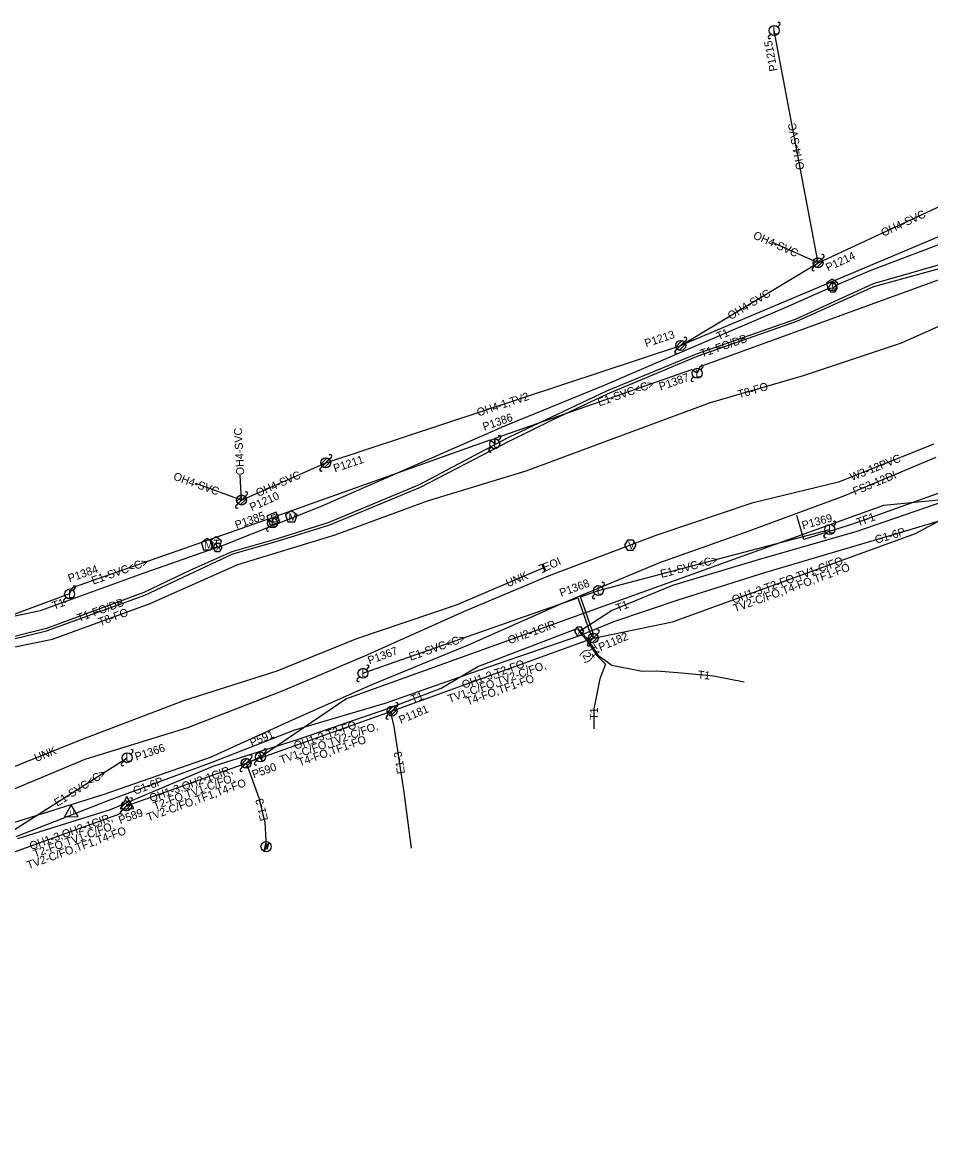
# Model space of a CAD drawing. Extents: x 2336688 to 2352634, y 362473 to 369571.
# Drawn here: x 2350587 to 2351041, y 368310 to 368866 of the extents above; entities that cross this region are included whole.
import ezdxf

# ---------------------------------------------------------------- set-up
doc = ezdxf.new("R2010")
doc.units = 0
for name, color, linetype in [('RD_EX_DV_Prop', 7, 'Continuous'), ('RD_EX_DV_TX_Prop', 7, 'Continuous'), ('RD_EX_RW', 7, 'Continuous'), ('RD_EX_RW_TX', 7, 'Continuous'), ('RD_HC_CL_Rel', 7, 'Continuous'), ('RD_HC_Data_Tic', 7, 'Continuous'), ('RD_PD_CstnLmt', 7, 'Continuous'), ('RD_PD_Final_TrvlWay', 7, 'Continuous'), ('RD_PD_Final_TX', 7, 'Continuous'), ('RD_PD_FOC', 7, 'Continuous'), ('RD_PD_PatLn2', 7, 'Continuous'), ('RD_PD_PatLn3', 7, 'Continuous'), ('RD_PD_PatLn4', 7, 'Continuous'), ('RD_SHT_ShtClip', 7, 'Continuous'), ('RD_Sketch1', 7, 'Continuous'), ('RD_Sketch2', 7, 'Continuous'), ('RD_Sketch5', 7, 'Continuous'), ('RD_Sketch8', 7, 'Continuous')]:
    doc.layers.add(name, color=color, linetype=linetype)

msp = doc.modelspace()

# ---------------------------------------------------------------- linework, layer by layer
at = {"layer": 'RD_EX_RW_TX'}
msp.add_line((2350684.98, 368603.53), (2350684.15, 368605.9), dxfattribs=at)
for points in [[(2350547.98, 368561.97), (2350596.49, 368572.11), (2350646, 368590.01), (2350683.45, 368603.19), (2350684.98, 368603.53), (2350685.71, 368603.81), (2350737.28, 368624.33), (2350782.62, 368644.22), (2350828.45, 368664.29), (2350878.61, 368684.87), (2350923.16, 368704), (2350969.39, 368723.81), (2350990.05, 368732.94), (2350992.44, 368733.22), (2350994.4, 368734.75), (2351011.06, 368741.96), (2351053.69, 368758.05)], [(2351057.77, 368748.3), (2351012.48, 368735.27), (2350973.53, 368717.4), (2350924.13, 368700.19), (2350879.33, 368681.7), (2350851.85, 368668.58), (2350829.97, 368658.39), (2350785.64, 368634.8), (2350740.56, 368616.04), (2350714.28, 368607.77), (2350692.2, 368601.39), (2350671.06, 368591.99), (2350648.19, 368580.98), (2350599.46, 368563.03), (2350571.6, 368556.05)], [(2350571.6, 368555.09), (2350599.59, 368561.91), (2350648.7, 368579.74), (2350692.54, 368600.36), (2350714.31, 368606.56), (2350741.1, 368614.8), (2350786.33, 368633.63), (2350830.68, 368656.6), (2350852.32, 368667.35), (2350879.75, 368680.28), (2350925.14, 368699.29), (2350974.31, 368716.57), (2351012.91, 368733.98), (2351058.97, 368746.67)], [(2350171.87, 368427.87), (2350217.94, 368444.86), (2350264.95, 368459.5), (2350312.55, 368474.5), (2350359.96, 368486.74), (2350398.97, 368499.58), (2350441.96, 368515.14), (2350504.54, 368534.47), (2350552.41, 368547.56), (2350602.53, 368557.75), (2350651.32, 368575.57), (2350695.05, 368595.12), (2350743.66, 368609.85), (2350789.93, 368626.9), (2350839.13, 368641.87), (2350884.51, 368658.74), (2350931.21, 368675.96), (2350977.7, 368689.48), (2351026.67, 368705.73), (2351072.69, 368726.31)], [(2350585.17, 368458.19), (2350631.55, 368472.55), (2350682.78, 368494.32), (2350725.46, 368507.84), (2350770.6, 368523.34), (2350796.76, 368533.17), (2350815.03, 368544.06), (2350864.65, 368563.02), (2350865.66, 368561.79), (2350866.64, 368562.26), (2350881.84, 368572.1), (2350912.46, 368584.65), (2350955.27, 368597.58), (2351004.61, 368611.63), (2351052.31, 368628.22)], [(2350865.66, 368561.79), (2350866.24, 368560.81), (2350868.94, 368557.77), (2350874.45, 368549.5), (2350878.83, 368545.22), (2350875.98, 368537.96), (2350872.99, 368522.86), (2350872.95, 368512.91)], [(2350865.66, 368561.79), (2350866.73, 368561.13), (2350869.44, 368558.17), (2350874.96, 368549.82), (2350881.96, 368544.69), (2350897.07, 368541.72), (2350904.37, 368541.89), (2350916.72, 368540.87), (2350932.83, 368539.33), (2350948.14, 368536.41)]]:
    msp.add_lwpolyline(points, dxfattribs=at)
for points in [[(2350991.99, 368737.61), (2350989.14, 368735.54), (2350990.23, 368732.19), (2350993.76, 368732.19), (2350994.85, 368735.54)], [(2350994.75, 368733.22), (2350993.59, 368735.22), (2350991.28, 368735.22), (2350990.13, 368733.22), (2350991.28, 368731.22), (2350993.59, 368731.22)], [(2350684.15, 368608.9), (2350681.29, 368606.83), (2350682.38, 368603.48), (2350685.91, 368603.48), (2350687, 368606.83)], [(2350687.29, 368603.53), (2350686.14, 368605.53), (2350683.83, 368605.53), (2350682.67, 368603.53), (2350683.83, 368601.53), (2350686.14, 368601.53)], [(2350867.97, 368561.79), (2350866.82, 368563.79), (2350864.51, 368563.79), (2350863.35, 368561.79), (2350864.51, 368559.79), (2350866.82, 368559.79)]]:
    msp.add_lwpolyline(points, close=True, dxfattribs=at)
at = {"layer": 'RD_HC_CL_Rel'}
msp.add_lwpolyline([(2350584.33, 368459.13), (2350630.35, 368477.17), (2350682.33, 368496.26), (2350723.55, 368512.36), (2350768.67, 368525.76), (2350815.63, 368542.18), (2350865.48, 368559.39), (2350883.5, 368566.67), (2350915.06, 368577.38), (2350958.43, 368591), (2351006.87, 368605.31), (2351056.9, 368620.23)], dxfattribs=at)
at = {"layer": 'RD_HC_Data_Tic'}
for p, q in [((2350964.86, 368863.63), (2350965.92, 368864.69)), ((2350960.27, 368859.04), (2350961.33, 368860.1)), ((2350982.56, 368745.17), (2350985.62, 368748.23)), ((2350983.21, 368744.05), (2350986.74, 368747.58)), ((2350986.74, 368747.58), (2350987.8, 368748.65)), ((2350982.14, 368742.99), (2350983.21, 368744.05)), ((2350984.33, 368743.4), (2350987.39, 368746.46)), ((2350913.55, 368701.66), (2350914.61, 368702.72)), ((2350913.96, 368703.84), (2350917.02, 368706.9)), ((2350914.61, 368702.72), (2350918.14, 368706.26)), ((2350915.73, 368702.08), (2350918.79, 368705.14)), ((2350918.14, 368706.26), (2350919.21, 368707.32)), ((2350926.36, 368692.34), (2350927.42, 368693.4)), ((2350921.76, 368687.74), (2350922.82, 368688.8)), ((2350825.22, 368657.13), (2350826.28, 368658.19)), ((2350820.62, 368652.53), (2350821.68, 368653.59)), ((2350736.61, 368645.21), (2350739.67, 368648.27)), ((2350737.26, 368644.09), (2350740.79, 368647.62)), ((2350740.79, 368647.62), (2350741.85, 368648.68)), ((2350736.19, 368643.03), (2350737.26, 368644.09)), ((2350738.38, 368643.44), (2350741.44, 368646.5)), ((2350694.15, 368624.44), (2350695.21, 368625.5)), ((2350694.56, 368626.62), (2350697.62, 368629.69)), ((2350695.21, 368625.5), (2350698.74, 368629.04)), ((2350696.33, 368624.86), (2350699.39, 368627.92)), ((2350698.74, 368629.04), (2350699.8, 368630.1)), ((2350709.6, 368612.99), (2350710.66, 368614.05)), ((2350714.19, 368617.58), (2350715.25, 368618.64)), ((2350992.61, 368614.3), (2350993.67, 368615.36)), ((2350988.01, 368609.7), (2350989.07, 368610.76)), ((2350612.86, 368582.08), (2350613.92, 368583.14)), ((2350872.4, 368579.2), (2350873.46, 368580.26)), ((2350876.99, 368583.8), (2350878.05, 368584.86)), ((2350608.26, 368577.48), (2350609.32, 368578.55)), ((2350870.31, 368557.66), (2350873.37, 368560.72)), ((2350870.95, 368556.54), (2350874.49, 368560.07)), ((2350872.07, 368555.89), (2350875.14, 368558.95)), ((2350874.49, 368560.07), (2350875.55, 368561.13)), ((2350869.89, 368555.48), (2350870.95, 368556.54)), ((2350759.39, 368542.45), (2350760.45, 368543.51)), ((2350754.8, 368537.86), (2350755.86, 368538.92)), ((2350773.92, 368523.58), (2350774.98, 368524.64)), ((2350769.32, 368518.98), (2350770.38, 368520.04)), ((2350769.73, 368521.16), (2350772.8, 368524.22)), ((2350770.38, 368520.04), (2350773.92, 368523.58)), ((2350771.5, 368519.39), (2350774.56, 368522.46)), ((2350637.02, 368495.69), (2350638.08, 368496.75)), ((2350641.61, 368500.29), (2350642.67, 368501.35)), ((2350696.8, 368495.06), (2350699.86, 368498.12)), ((2350697.45, 368493.94), (2350700.98, 368497.47)), ((2350700.98, 368497.47), (2350702.04, 368498.53)), ((2350703.56, 368496.05), (2350704.63, 368497.11)), ((2350708.16, 368500.65), (2350709.22, 368501.71)), ((2350696.39, 368492.88), (2350697.45, 368493.94)), ((2350698.57, 368493.29), (2350701.63, 368496.35)), ((2350637.03, 368473.78), (2350640.09, 368476.84)), ((2350637.68, 368472.66), (2350641.21, 368476.19)), ((2350638.8, 368472.01), (2350641.86, 368475.07)), ((2350641.21, 368476.19), (2350642.28, 368477.25)), ((2350636.62, 368471.6), (2350637.68, 368472.66))]:
    msp.add_line(p, q, dxfattribs=at)
msp.add_lwpolyline([(2350706, 368500.89), (2350706.83, 368498.87), (2350705.37, 368499.68), (2350707.24, 368496.99), (2350707.24, 368496.99), (2350706.04, 368499.09), (2350707.42, 368498.29)], close=True, dxfattribs=at)
for centre in [(2350963.09, 368861.87), (2350984.97, 368745.82), (2350916.38, 368704.49), (2350924.59, 368690.57), (2350823.45, 368655.36), (2350739.02, 368645.86), (2350696.97, 368627.27), (2350712.43, 368615.82), (2350990.84, 368612.53), (2350611.09, 368580.31), (2350875.22, 368582.03), (2350872.72, 368558.3), (2350757.63, 368540.68), (2350772.15, 368521.81), (2350639.85, 368498.52), (2350699.22, 368495.71), (2350706.39, 368498.88), (2350639.45, 368474.42)]:
    msp.add_circle(centre, 2.5, dxfattribs=at)
for centre, start, end in [((2350965.39, 368865.22), 315, 135), ((2350960.8, 368858.51), 135, 315), ((2350987.27, 368749.18), 315, 135), ((2350982.67, 368742.46), 135, 315), ((2350918.68, 368707.85), 315, 135), ((2350914.08, 368701.13), 135, 315), ((2350926.89, 368693.93), 315, 135), ((2350922.29, 368687.21), 135, 315), ((2350825.75, 368658.72), 315, 135), ((2350821.15, 368652), 135, 315), ((2350741.32, 368649.21), 315, 135), ((2350736.72, 368642.5), 135, 315), ((2350699.27, 368630.63), 315, 135), ((2350694.68, 368623.91), 135, 315), ((2350714.72, 368619.17), 315, 135), ((2350993.14, 368615.89), 315, 135), ((2350710.13, 368612.46), 135, 315), ((2350988.54, 368609.17), 135, 315), ((2350877.52, 368585.39), 315, 135), ((2350613.39, 368583.67), 315, 135), ((2350608.79, 368576.95), 135, 315), ((2350872.93, 368578.67), 135, 315), ((2350875.02, 368561.66), 315, 135), ((2350870.42, 368554.95), 135, 315), ((2350759.92, 368544.04), 315, 135), ((2350755.33, 368537.33), 135, 315), ((2350774.45, 368525.17), 315, 135), ((2350769.85, 368518.45), 135, 315), ((2350642.14, 368501.88), 315, 135), ((2350708.69, 368502.24), 315, 135), ((2350701.51, 368499.06), 315, 135), ((2350637.55, 368495.16), 135, 315), ((2350696.92, 368492.35), 135, 315), ((2350704.09, 368495.52), 135, 315), ((2350641.75, 368477.78), 315, 135), ((2350637.15, 368471.07), 135, 315)]:
    msp.add_arc(centre, 0.75, start, end, dxfattribs=at)
at = {"layer": 'RD_PD_Final_TrvlWay'}
for points in [[(2351152.66, 368771.86), (2351150.34, 368773.72), (2351066.03, 368744.69), (2351065.02, 368741.68), (2351062.36, 368743.39), (2350925.92, 368693.73), (2350924.59, 368690.57), (2350921.77, 368692.25), (2350823.59, 368658.07), (2350823.45, 368655.36), (2350821.04, 368657.17), (2350712.58, 368618.54), (2350712.43, 368615.82), (2350710.28, 368617.73), (2350612.32, 368583.41), (2350611.09, 368580.31), (2350556.98, 368560.45), (2350499.18, 368544.19), (2350503.41, 368546.65), (2350527.75, 368553.5), (2350557.82, 368562.03), (2350555.37, 368575.95), (2350556.68, 368579.27)], [(2350757.63, 368540.68), (2350864.91, 368578.41), (2350871.14, 368560.68), (2350872.72, 368558.3), (2350872.46, 368561.15), (2350866.23, 368578.87), (2350875.22, 368582.03), (2350990.84, 368612.53)], [(2350772.15, 368521.81), (2350771.61, 368520.42), (2350773.07, 368514.08), (2350778.11, 368481.36), (2350781.65, 368453.29)], [(2350529.28, 368444.39), (2350575.55, 368457.63), (2350639.85, 368498.52)], [(2350699.22, 368495.71), (2350699.82, 368494.64), (2350705.56, 368478.53), (2350708.55, 368466.06), (2350709.23, 368454.06)]]:
    msp.add_lwpolyline(points, dxfattribs=at)
for points in [[(2350714.33, 368621.13), (2350709.63, 368619.42), (2350711.34, 368614.72), (2350716.03, 368616.43)], [(2350710.62, 368456.12), (2350709.61, 368452.67), (2350709.11, 368454.54), (2350708.35, 368451.71), (2350709.04, 368455.62), (2350709.6, 368453.68)]]:
    msp.add_lwpolyline(points, close=True, dxfattribs=at)
msp.add_circle((2350709.23, 368454.06), 2.55, dxfattribs=at)
at = {"layer": 'RD_PD_PatLn3'}
for points in [[(2350569.2, 368488.37), (2350617.02, 368507.64), (2350668.18, 368527.03), (2350714.72, 368541.98), (2350754.57, 368558.07), (2350804.34, 368574.84), (2350847.72, 368593.34)], [(2350845.55, 368594.59), (2350846.93, 368595.18), (2350848.5, 368591.5), (2350847.12, 368590.91)]]:
    msp.add_lwpolyline(points, dxfattribs=at)
for points in [[(2350611.88, 368475.01), (2350608.5, 368468.97), (2350615.43, 368469.06)], [(2350639.66, 368479.07), (2350636.28, 368473.03), (2350643.2, 368473.12)]]:
    msp.add_lwpolyline(points, close=True, dxfattribs=at)
at = {"layer": 'RD_SHT_ShtClip'}
for p, q in [((2350984.97, 368745.82), (2350963.09, 368861.87)), ((2351197.21, 368822.78), (2350916.38, 368704.49)), ((2350984.97, 368745.82), (2351070.54, 368785.56)), ((2350984.97, 368745.82), (2350961.83, 368756.06)), ((2350916.38, 368704.49), (2350984.97, 368745.82)), ((2350739.02, 368645.86), (2350916.38, 368704.49)), ((2350696.97, 368627.27), (2350739.02, 368645.86)), ((2350696.97, 368627.27), (2350696.34, 368639.63)), ((2350696.97, 368627.27), (2350674.05, 368635.54)), ((2350872.72, 368558.3), (2350772.15, 368521.81)), ((2350772.15, 368521.81), (2350699.22, 368495.71)), ((2350699.22, 368495.71), (2350706.39, 368498.88)), ((2350639.45, 368474.42), (2350699.22, 368495.71))]:
    msp.add_line(p, q, dxfattribs=at)
for points in [[(2350706.39, 368498.88), (2350749.08, 368527.9), (2351017.85, 368624.75), (2351069.24, 368629.63)], [(2350872.72, 368558.3), (2350912.32, 368566.46), (2351033.64, 368610.49), (2351069.24, 368629.63)], [(2350577.9, 368452.25), (2350583.51, 368451.44), (2350635.64, 368470.23), (2350639.45, 368474.42)]]:
    msp.add_lwpolyline(points, dxfattribs=at)
at = {"layer": 'RD_Sketch2'}
msp.add_lwpolyline([(2351042.86, 368655.18), (2350995.25, 368636.19), (2350951.94, 368625.72), (2350904.41, 368609.66), (2350850.2, 368589.13), (2350807.88, 368571.45), (2350758.45, 368549.2), (2350717.62, 368531.89), (2350669.89, 368513.41), (2350618.71, 368497.66), (2350574.37, 368479.11), (2350524.2, 368457.7), (2350508, 368452.18), (2350504.2, 368450.53), (2350448.23, 368434.31), (2350382.35, 368413.96), (2350336.49, 368399.02), (2350285.67, 368383.39), (2350239.06, 368369.9), (2350196.44, 368356.53), (2350109.57, 368328)], dxfattribs=at)
for points in [[(2350721.83, 368621.94), (2350718.93, 368619.83), (2350720.04, 368616.42), (2350723.62, 368616.42), (2350724.73, 368619.83)], [(2350679.82, 368607.96), (2350676.92, 368605.85), (2350678.03, 368602.44), (2350681.61, 368602.44), (2350682.72, 368605.85)], [(2350894.13, 368604.69), (2350892.68, 368607.19), (2350889.8, 368607.19), (2350888.35, 368604.69), (2350889.8, 368602.19), (2350892.68, 368602.19)]]:
    msp.add_lwpolyline(points, close=True, dxfattribs=at)
at = {"layer": 'RD_Sketch5'}
msp.add_lwpolyline([(2350116.54, 368309.62), (2350157.85, 368325.74), (2350201.04, 368338.25), (2350246.21, 368351.09), (2350290.88, 368366.1), (2350342.68, 368382.19), (2350386.37, 368397.34), (2350435.33, 368415.03), (2350480.68, 368428.89), (2350526.02, 368446.27), (2350580.59, 368465.31), (2350628.33, 368480.35), (2350681.49, 368498.77), (2350722.35, 368517.44), (2350762.63, 368535.33), (2350810.28, 368554.98), (2350857.34, 368575.64), (2350905.94, 368596.06), (2350950.65, 368611.89), (2350997.52, 368629.24), (2351044.06, 368648.74)], dxfattribs=at)
at = {"layer": 'RD_Sketch8'}
msp.add_lwpolyline([(2351199.73, 368684.73), (2351197.73, 368684.53), (2351193.65, 368682.92), (2351193.65, 368682.92), (2351190.74, 368682.07), (2351145.06, 368665.59), (2351101.58, 368650.11), (2351050.48, 368632.5), (2351002.12, 368615.17), (2350977.81, 368607.48), (2350974.44, 368619.46)], dxfattribs=at)

# ---------------------------------------------------------------- texts
at = {"layer": 'RD_EX_DV_Prop'}
for s, rotation, p in [('E1-SVC<C>', 19.3138, (2350875.67, 368674.02)), ('E1-SVC<C>', 19.3138, (2350622.84, 368584.97)), ('E1-SVC<C>', 14.7775, (2350906.78, 368588.29)), ('E1-SVC<C>', 19.3719, (2350781.42, 368546.93)), ('E1-3', 99.315, (2350778.69, 368490.72)), ('E1-SVC<C>', 32.4591, (2350604.95, 368473.96)), ('E1-3', 103.4989, (2350710.27, 368467.46))]:
    msp.add_text(s, height=4, rotation=rotation, dxfattribs=at).set_placement(p)
at = {"layer": 'RD_EX_DV_TX_Prop'}
for s, rotation, p in [('P1215', 100.6768, (2350964.76, 368841.86)), ('P1214', 24.9124, (2350989.97, 368741.43)), ('P1213', 18.2941, (2350899.08, 368703.52)), ('P1387', 19.3079, (2350906.35, 368681.89)), ('P1386', 19.3079, (2350818.26, 368661.88)), ('P1211', 18.2941, (2350743.62, 368641.08)), ('P1210', 23.8447, (2350702.09, 368621.66)), ('P1385', 19.3079, (2350694.5, 368612.78)), ('P1369', 14.9923, (2350977.49, 368612.61)), ('P1384', 19.3079, (2350611.08, 368586.07)), ('P1368', 20.0359, (2350856.67, 368578.87)), ('P1182', 22.8929, (2350876.28, 368551.67)), ('P1367', 20.0359, (2350760.85, 368545.05)), ('P1181', 22.8929, (2350776.57, 368515.37)), ('P591', 22.8929, (2350702.11, 368503.93)), ('P1366', 18.2724, (2350644.44, 368496.99)), ('P590', 19.5979, (2350703.07, 368488.16)), ('P589', 19.5979, (2350636.37, 368465.27))]:
    msp.add_text(s, height=4, rotation=rotation, dxfattribs=at).set_placement(p)
at = {"layer": 'RD_EX_RW'}
for s, rotation, p in [('T1-FO/DB', 19.3605, (2350926.97, 368698.38)), ('T1', 23.2044, (2350935.22, 368706.99)), ('T8-FO', 16.2164, (2350945.56, 368678.05)), ('T1', 19.874, (2350603.2, 368572.41)), ('T1-FO/DB', 19.9576, (2350615.72, 368566.28)), ('T1', 22.2805, (2350884.99, 368571.23)), ('T8-FO', 20.0681, (2350626.24, 368564.28)), ('(2)', 303.5987, (2350866.11, 368551.06)), ('T1', 303.5987, (2350869.77, 368553.29)), ('T1', 354.537, (2350924.73, 368538.1)), ('T1', 20.6012, (2350782.47, 368525.66)), ('T1', 89.8042, (2350874.97, 368517.43))]:
    msp.add_text(s, height=4, rotation=rotation, dxfattribs=at).set_placement(p)
at = {"layer": 'RD_EX_RW_TX'}
for s, height, p in [('T', 3.75, (2350990.76, 368732.39)), ('X', 3, (2350991.49, 368731.72)), ('T', 3.75, (2350682.92, 368603.68)), ('X', 3, (2350684.04, 368602.03)), ('X', 3, (2350864.72, 368560.29))]:
    msp.add_text(s, height=height, dxfattribs=at).set_placement(p)
at = {"layer": 'RD_HC_Data_Tic'}
for p in [(2350962.28, 368859.93), (2350923.78, 368688.64), (2350822.64, 368653.42), (2350711.62, 368613.88), (2350990.03, 368610.6), (2350610.28, 368578.38), (2350874.41, 368580.1), (2350756.82, 368538.75), (2350639.04, 368496.59)]:
    msp.add_text('L', height=4, rotation=360, dxfattribs=at).set_placement(p)
at = {"layer": 'RD_PD_CstnLmt'}
msp.add_text('W3-12PVC', height=4, rotation=21.7516, dxfattribs=at).set_placement((2351001.9, 368636.69))
at = {"layer": 'RD_PD_Final_TrvlWay'}
msp.add_text('E', height=4, rotation=19.9826, dxfattribs=at).set_placement((2350712.38, 368615.63))
at = {"layer": 'RD_PD_Final_TX'}
for rotation, p in [(23.1062, (2350830.05, 368583.63)), (21.9479, (2350594.39, 368496.36))]:
    msp.add_text('UNK', height=4, rotation=rotation, dxfattribs=at).set_placement(p)
at = {"layer": 'RD_PD_FOC'}
msp.add_text('TF1', height=4, rotation=19.7229, dxfattribs=at).set_placement((2351004.99, 368614.07))
at = {"layer": 'RD_PD_PatLn2'}
for rotation, p in [(16.6036, (2351014.06, 368605.37)), (20.1616, (2350643.65, 368479.92))]:
    msp.add_text('G1-6P', height=4, rotation=rotation, dxfattribs=at).set_placement(p)
at = {"layer": 'RD_PD_PatLn3'}
for s, height, rotation, p in [('EOI', 4, 23.1062, (2350848.49, 368591.5)), ('U', 2.4, 0.7793, (2350638.97, 368473.86)), ('U', 2.4, 0.7793, (2350611.2, 368469.8))]:
    msp.add_text(s, height=height, rotation=rotation, dxfattribs=at).set_placement(p)
at = {"layer": 'RD_PD_PatLn4'}
for s, rotation, p in [('OH4-SVC', 100.6768, (2350978.19, 368792.59)), ('OH4-SVC', 24.9124, (2351017.6, 368758.76)), ('OH4-SVC', 336.1347, (2350952.21, 368758.13)), ('OH4-SVC', 31.0677, (2350941.32, 368717.18)), ('OH4-1,TV2', 18.2941, (2350815.29, 368668.96)), ('OH4-SVC', 92.9257, (2350698.34, 368639.73)), ('OH4-SVC', 23.8447, (2350705.22, 368628.73)), ('OH4-SVC', 340.1729, (2350662.56, 368637.55)), ('OH1-3,T2-FO,TV1-C/FO,', 19.9486, (2350942.81, 368575.4)), ('TV2-C/FO,T4-FO,TF1-FO', 19.9486, (2350943.5, 368571.1)), ('OH2-1CIR', 19.8167, (2350830.79, 368555.11)), ('OH1-3,T2-FO,', 19.5276, (2350807.9, 368532.92)), ('TV1-C/FO,TV2-C/FO,', 19.5276, (2350800.83, 368525.87)), ('T4-FO,TF1-FO', 19.5276, (2350809.98, 368524.58)), ('TV1-C/FO,TV2-C/FO,', 19.5276, (2350716.86, 368495.38)), ('OH1-3,T2-FO,', 19.5276, (2350723.93, 368502.43)), ('T4-FO,TF1-FO', 19.5276, (2350726.01, 368494.08)), ('OH1-3,OH2-1CIR,', 19.8188, (2350651.78, 368476.24)), ('TV2-C/FO,TF1,T4-FO', 19.8188, (2350650.44, 368466.66)), ('T2-FO,TV1-C/FO,', 19.8188, (2350653.66, 368472.37)), ('OH1-3,OH2-1CIR,', 19.8188, (2350591.87, 368452.33)), ('TV2-C/FO,TF1,T4-FO', 19.8188, (2350590.53, 368442.75)), ('T2-FO,TV1-C/FO,', 19.8188, (2350593.75, 368448.46))]:
    msp.add_text(s, height=4, rotation=rotation, dxfattribs=at).set_placement(p)
at = {"layer": 'RD_Sketch1'}
msp.add_text('FS3-12DI', height=4, rotation=22.7329, dxfattribs=at).set_placement((2351003.37, 368629.52))
at = {"layer": 'RD_Sketch2'}
for s, p in [('M', (2350720.46, 368616.89)), ('M', (2350678.45, 368602.91)), ('V', (2350890.03, 368602.81))]:
    msp.add_text(s, height=3.75, dxfattribs=at).set_placement(p)

doc.saveas('drawing.dxf')
